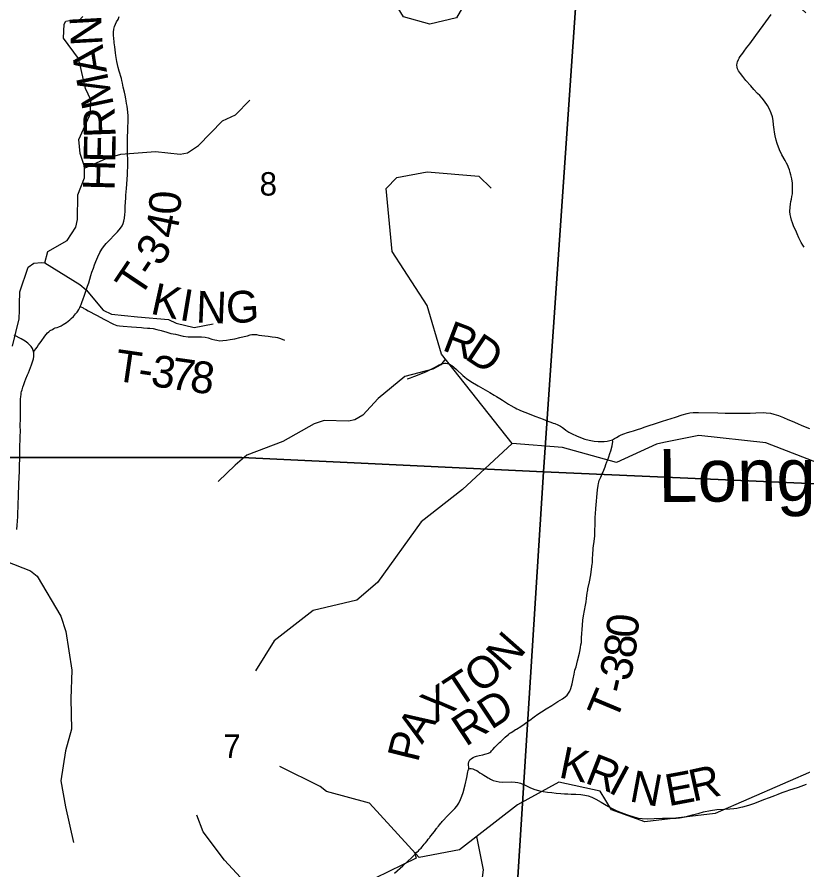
# Model space of a CAD drawing. Extents: x 0 to 34, y 0 to 22.
# Drawn here: x 25.483 to 26.889, y 16.271 to 17.797 of the extents above; entities that cross this region are included whole.
import ezdxf

# ---------------------------------------------------------------- set-up
doc = ezdxf.new("R2010")
doc.units = 0
for name, color, linetype in [('GM_X_County_Road', 7, 'Continuous'), ('GM_X_County_Road_Text', 7, 'Continuous'), ('GM_X_Minor_River', 7, 'Continuous'), ('GM_X_Minor_River_Text', 7, 'Continuous'), ('GM_X_Section', 7, 'Continuous'), ('GM_X_Section_Text', 7, 'Continuous'), ('GM_X_Township_Road', 7, 'Continuous'), ('GM_X_Township_Road_Text', 7, 'Continuous')]:
    doc.layers.add(name, color=color, linetype=linetype)

msp = doc.modelspace()

# ---------------------------------------------------------------- linework, layer by layer
at = {"layer": 'GM_X_County_Road'}
for points in [[(26.8908, 17.3848), (26.8887, 17.3883), (26.8856, 17.3932), (26.8818, 17.4015), (26.8787, 17.4086), (26.876, 17.4149), (26.8728, 17.4215), (26.87, 17.4287), (26.8685, 17.4334), (26.8671, 17.4387), (26.8659, 17.4435), (26.8654, 17.4488), (26.8658, 17.4566), (26.8667, 17.4622), (26.8675, 17.4669), (26.8683, 17.4711), (26.8692, 17.4757), (26.87, 17.4806), (26.8705, 17.4864), (26.8705, 17.4942), (26.8701, 17.4997), (26.8691, 17.5073), (26.8672, 17.5143), (26.866, 17.5186), (26.8646, 17.5234), (26.8632, 17.5273), (26.8616, 17.5314), (26.8596, 17.5354), (26.8573, 17.5398), (26.8514, 17.5502), (26.8472, 17.5593), (26.8427, 17.5702), (26.8409, 17.5763), (26.8392, 17.5844), (26.8382, 17.5908), (26.8375, 17.5957), (26.8365, 17.6037), (26.8356, 17.6115), (26.8343, 17.6179), (26.8322, 17.6246), (26.8291, 17.6317), (26.8253, 17.6386), (26.8202, 17.6463), (26.8158, 17.6516), (26.8116, 17.6562), (26.8077, 17.6602), (26.8013, 17.667), (26.7954, 17.6734), (26.787, 17.6833), (26.7811, 17.6905), (26.7769, 17.6959), (26.7737, 17.7006), (26.772, 17.7041), (26.7711, 17.7072), (26.7708, 17.7104), (26.771, 17.7143), (26.7716, 17.7168), (26.7733, 17.721), (26.7746, 17.7232), (26.7768, 17.7262), (26.7788, 17.7289), (26.7812, 17.7321), (26.7835, 17.7356), (26.7881, 17.7415), (26.7936, 17.7491), (26.8046, 17.7639), (26.8175, 17.7816), (26.8321, 17.8013)], [(25.4822, 16.88), (25.4829, 16.8874), (25.4835, 16.8948), (25.4839, 16.9029), (25.4842, 16.9128), (25.4843, 16.9171), (25.4845, 16.9252), (25.4849, 16.9395), (25.4858, 16.9618), (25.4867, 16.9842), (25.487, 16.9947), (25.4873, 17.0063), (25.4877, 17.0239), (25.4883, 17.0456), (25.4885, 17.0561), (25.4884, 17.0648), (25.4887, 17.0791), (25.4886, 17.1045), (25.4889, 17.1131), (25.4893, 17.118), (25.4897, 17.1211), (25.4901, 17.1241), (25.4908, 17.127), (25.4915, 17.13), (25.4929, 17.1347), (25.4946, 17.1393), (25.4965, 17.1445), (25.4984, 17.1491), (25.5013, 17.1564), (25.5031, 17.1604), (25.5048, 17.1646), (25.5068, 17.1698), (25.5086, 17.1744), (25.5104, 17.1797), (25.512, 17.1851), (25.5125, 17.1895), (25.5127, 17.192), (25.5125, 17.1958), (25.5121, 17.1978), (25.5116, 17.2001), (25.5103, 17.2036), (25.5079, 17.2074), (25.5063, 17.2093), (25.502, 17.2131), (25.497, 17.2168), (25.49, 17.2209), (25.4772, 17.2275)], [(26.291, 16.4508), (26.2917, 16.4514), (26.2932, 16.4519), (26.2951, 16.4522), (26.2983, 16.4516), (26.302, 16.45), (26.3051, 16.4483), (26.3078, 16.4467), (26.3109, 16.4446), (26.3143, 16.4424), (26.3181, 16.44), (26.3209, 16.4383), (26.3256, 16.4353), (26.3278, 16.434), (26.33, 16.4328), (26.3345, 16.4309), (26.3399, 16.4292), (26.3453, 16.4282), (26.3519, 16.4278), (26.3674, 16.4282), (26.3739, 16.4279), (26.3785, 16.4272), (26.3835, 16.4257), (26.3918, 16.4222), (26.3968, 16.4198), (26.4015, 16.4178), (26.409, 16.4147), (26.4155, 16.4128), (26.4201, 16.4118), (26.4241, 16.411), (26.4317, 16.4098), (26.4393, 16.4089), (26.4473, 16.408), (26.4557, 16.4074), (26.4622, 16.4069), (26.4684, 16.4067), (26.4742, 16.4065), (26.4822, 16.4063), (26.4913, 16.4056), (26.4984, 16.4047), (26.5048, 16.403), (26.5112, 16.4006), (26.5184, 16.3972), (26.5281, 16.3917), (26.534, 16.3883), (26.541, 16.3842), (26.5475, 16.3806), (26.556, 16.3765), (26.5635, 16.3733), (26.5732, 16.3696), (26.5784, 16.368), (26.5847, 16.3661), (26.5943, 16.3634), (26.6012, 16.3625), (26.6111, 16.3622), (26.6229, 16.3626), (26.6378, 16.3632), (26.6434, 16.3634), (26.6546, 16.3631), (26.662, 16.3633), (26.6682, 16.3639), (26.6781, 16.3657), (26.6914, 16.369), (26.6962, 16.3703), (26.703, 16.3721), (26.7111, 16.3743), (26.7232, 16.3768), (26.7351, 16.3785), (26.7475, 16.3794), (26.7582, 16.3802), (26.7651, 16.3808), (26.7704, 16.3813), (26.778, 16.383), (26.7814, 16.3837), (26.7918, 16.3867), (26.8027, 16.3903), (26.8191, 16.3964), (26.8288, 16.4001), (26.8389, 16.404), (26.8448, 16.4062), (26.8518, 16.4089), (26.8587, 16.4115), (26.8655, 16.4138), (26.8714, 16.4158), (26.8811, 16.419), (26.8954, 16.4243)], [(26.158, 16.2647), (26.1727, 16.2779), (26.1814, 16.2859), (26.1889, 16.293), (26.1947, 16.2986), (26.1982, 16.3023), (26.2009, 16.3048), (26.2024, 16.3065), (26.2041, 16.3082), (26.2057, 16.3098), (26.2068, 16.3111), (26.2075, 16.312), (26.2095, 16.3142), (26.2113, 16.3166), (26.2133, 16.3189), (26.2163, 16.3227), (26.2185, 16.3256), (26.2196, 16.3271), (26.2204, 16.328), (26.2215, 16.3294), (26.226, 16.3351), (26.2293, 16.3395), (26.2322, 16.3432), (26.2333, 16.3446), (26.2344, 16.346), (26.2351, 16.3469), (26.2365, 16.3488), (26.2386, 16.3514), (26.2408, 16.3542), (26.242, 16.3556), (26.2432, 16.357), (26.2445, 16.3583), (26.2456, 16.3597), (26.2469, 16.361), (26.2486, 16.3629), (26.2494, 16.3637), (26.2511, 16.3655), (26.2529, 16.3672), (26.2567, 16.3712), (26.2612, 16.3757), (26.2659, 16.3807), (26.2695, 16.385), (26.2729, 16.3902), (26.2762, 16.3967), (26.2787, 16.4028), (26.2807, 16.4092), (26.2843, 16.423), (26.2874, 16.436), (26.2892, 16.4463), (26.2897, 16.4488), (26.2904, 16.4503), (26.291, 16.4508)]]:
    msp.add_lwpolyline(points, dxfattribs=at)
at = {"layer": 'GM_X_Minor_River'}
for points in [[(26.8939, 17.8041), (26.8093, 17.8831), (26.7577, 17.9938), (26.6748, 18.0364), (26.663, 18.0393), (26.4885, 17.9971), (26.3926, 17.9568), (26.3196, 17.8836), (26.2691, 17.7955), (26.221, 17.7841), (26.1738, 17.7969), (26.1172, 17.8898)], [(25.4745, 17.2077), (25.4863, 17.2567), (25.487, 17.272), (25.487, 17.283), (25.4878, 17.305), (25.5022, 17.3492), (25.5128, 17.3564), (25.5261, 17.3576), (25.5325, 17.3572), (25.5375, 17.377), (25.572, 17.3971), (25.5875, 17.4207), (25.591, 17.4344), (25.5913, 17.4785), (25.6035, 17.509), (25.6035, 17.5291), (25.5952, 17.5523), (25.5933, 17.5778), (25.6122, 17.62), (25.6141, 17.6265), (25.6145, 17.6485), (25.6051, 17.669), (25.5956, 17.7108), (25.5926, 17.7226), (25.5657, 17.7591), (25.5668, 17.7842), (25.5699, 17.7895), (25.5763, 17.7907), (25.5934, 17.7899), (25.6002, 17.7975)], [(25.6035, 17.5265), (25.6419, 17.5439), (25.6682, 17.5511), (25.7302, 17.5563), (25.7746, 17.5516), (25.7876, 17.554), (25.8075, 17.5667), (25.8499, 17.6109), (25.8732, 17.622), (25.8991, 17.6483)], [(26.3684, 17.0338), (26.2421, 17.1937), (26.2163, 17.2807), (26.1539, 17.377), (26.1433, 17.49), (26.162, 17.5099), (26.2162, 17.5195), (26.3089, 17.512), (26.3308, 17.4905)], [(25.5325, 17.3572), (25.5947, 17.318), (25.6063, 17.3084), (25.6369, 17.2722), (25.6513, 17.2648), (25.6983, 17.2604), (25.7537, 17.2558), (25.7673, 17.2492), (25.7995, 17.2411), (25.8337, 17.2479)], [(26.249, 17.1849), (26.2407, 17.1743), (26.2265, 17.1665), (26.1762, 17.1535), (26.1285, 17.1139), (26.1015, 17.0846), (26.0873, 17.076), (26.0759, 17.0735), (26.0322, 17.0749), (26.0143, 17.0687), (25.958, 17.0372), (25.8935, 17.0126), (25.8727, 16.995), (25.8423, 16.9654)], [(26.9441, 16.9877), (26.8224, 17.0349), (26.7026, 17.0482), (26.6397, 17.0355), (26.6269, 17.0327), (26.5552, 16.9998), (26.4584, 17.0267), (26.3683, 17.0338), (26.2798, 16.9514), (26.2058, 16.8935), (26.1275, 16.785), (26.0907, 16.7535), (26.0124, 16.7346), (25.9425, 16.6805), (25.9094, 16.6266)], [(25.421, 16.8113), (25.4622, 16.8229), (25.5066, 16.8058), (25.5187, 16.796), (25.5607, 16.7249), (25.5698, 16.6975), (25.5804, 16.628), (25.5785, 16.5766), (25.58, 16.5226), (25.5694, 16.4835), (25.5606, 16.4302), (25.569, 16.3835), (25.5837, 16.32)], [(27.2498, 16.6488), (27.1456, 16.6153), (27.0809, 16.5676), (26.9976, 16.5244), (26.9124, 16.4504), (26.732, 16.3717), (26.6058, 16.3569), (26.5466, 16.378), (26.5261, 16.4116), (26.4522, 16.4277), (26.378, 16.3871), (26.2742, 16.3065), (26.2023, 16.293), (26.1133, 16.3901), (26.0364, 16.4107), (26.0249, 16.42), (25.953, 16.4558)], [(26.1935, 16.3026), (26.1966, 16.2917), (26.1235, 16.2558), (26.036, 16.2415), (26.0085, 16.2365), (25.9717, 16.2351), (25.9486, 16.2438), (25.8827, 16.2572), (25.8535, 16.288), (25.8155, 16.3387), (25.8045, 16.3689)], [(26.3049, 16.3303), (26.3169, 16.2708), (26.3031, 16.164), (26.2206, 15.9716), (26.2072, 15.921)]]:
    msp.add_lwpolyline(points, dxfattribs=at)
at = {"layer": 'GM_X_Section'}
for points in [[(25.4369, 18.0387), (25.9143, 18.0162), (26.4949, 18.0036), (26.4248, 16.9831), (25.8848, 17.0085), (25.3722, 17.0086), (25.3999, 17.4262), (25.4267, 17.8394)], [(26.4949, 18.0036), (27.546, 17.9583), (27.5355, 17.7931), (27.4974, 17.1618), (27.484, 16.9363), (26.4248, 16.9831)], [(26.4248, 16.9831), (26.3613, 15.9846), (25.3091, 16.0203), (25.3722, 17.0086), (25.8848, 17.0085)], [(27.484, 16.9363), (27.4673, 16.6748), (27.4216, 15.9328), (26.3734, 15.9843), (26.3613, 15.9846), (26.4248, 16.9831)]]:
    msp.add_lwpolyline(points, close=True, dxfattribs=at)
at = {"layer": 'GM_X_Township_Road'}
for points in [[(25.5121, 17.1978), (25.5183, 17.2062), (25.5212, 17.2102), (25.5257, 17.2161), (25.5324, 17.2258), (25.5369, 17.2315), (25.5392, 17.2336), (25.5419, 17.2357), (25.5457, 17.2379), (25.5484, 17.2392), (25.5509, 17.2404), (25.5541, 17.2415), (25.5572, 17.2424), (25.5615, 17.2444), (25.5652, 17.2464), (25.571, 17.25), (25.5742, 17.2526), (25.5768, 17.2551), (25.5796, 17.2575), (25.5834, 17.261), (25.5874, 17.2654), (25.5886, 17.267), (25.5903, 17.2689), (25.5914, 17.2706), (25.593, 17.2736), (25.5946, 17.2768), (25.5956, 17.2788), (25.5971, 17.2824), (25.5991, 17.2875), (25.6004, 17.291), (25.6033, 17.2991), (25.607, 17.3097), (25.6089, 17.3154), (25.6108, 17.3209), (25.6146, 17.334), (25.6166, 17.3401), (25.6191, 17.3475), (25.6214, 17.3535), (25.6235, 17.3591), (25.627, 17.3676), (25.6308, 17.3754), (25.6342, 17.3813), (25.637, 17.3853), (25.6422, 17.3915), (25.6489, 17.3988), (25.6559, 17.4058), (25.6623, 17.4125), (25.6674, 17.4187), (25.6705, 17.4234), (25.6725, 17.4273), (25.6739, 17.4315), (25.6749, 17.437), (25.6756, 17.4432), (25.6758, 17.4485), (25.676, 17.4538), (25.6763, 17.4594), (25.6765, 17.4637), (25.6767, 17.4661), (25.6771, 17.4725), (25.6775, 17.4779), (25.6784, 17.4899), (25.6801, 17.5143), (25.6806, 17.5345), (25.6806, 17.5412), (25.6803, 17.5517), (25.6802, 17.5554), (25.6801, 17.5659), (25.6803, 17.5833), (25.6805, 17.5919), (25.6808, 17.6011), (25.6813, 17.6078), (25.6816, 17.6134), (25.6814, 17.6198), (25.681, 17.6263), (25.6804, 17.6318), (25.6794, 17.6373), (25.6787, 17.6422), (25.6778, 17.647), (25.6771, 17.6507), (25.676, 17.6567), (25.6748, 17.6622), (25.6726, 17.6715), (25.671, 17.6786), (25.67, 17.6831), (25.6692, 17.6866), (25.6651, 17.7), (25.6635, 17.7066), (25.6622, 17.712), (25.6613, 17.7175), (25.6601, 17.7242), (25.6595, 17.7279), (25.659, 17.7328), (25.6575, 17.7437), (25.6565, 17.7506), (25.6563, 17.7536), (25.656, 17.7573), (25.6554, 17.7654), (25.6554, 17.7697), (25.6558, 17.7752), (25.657, 17.7799), (25.659, 17.7843), (25.6607, 17.7881), (25.6634, 17.7925), (25.6646, 17.7959), (25.6653, 17.7978)], [(25.5956, 17.2788), (25.6006, 17.2762), (25.6022, 17.2753), (25.6049, 17.2739), (25.6097, 17.2712), (25.6245, 17.2632), (25.6389, 17.2558), (25.6552, 17.2472), (25.661, 17.2449), (25.6656, 17.244), (25.6724, 17.2436), (25.6874, 17.2422), (25.7052, 17.241), (25.709, 17.2407), (25.7157, 17.2403), (25.7204, 17.2398), (25.726, 17.2392), (25.7326, 17.2379), (25.7404, 17.2357), (25.7505, 17.2326), (25.7575, 17.2305), (25.7658, 17.2291), (25.7799, 17.2259), (25.7888, 17.2246), (25.7967, 17.2244), (25.805, 17.2245), (25.8127, 17.2243), (25.819, 17.2237), (25.8248, 17.2227), (25.8314, 17.2206), (25.8362, 17.2193), (25.8403, 17.2184), (25.8455, 17.2175), (25.851, 17.2177), (25.8572, 17.2186), (25.8639, 17.2199), (25.872, 17.2212), (25.8815, 17.2232), (25.8891, 17.2249), (25.8949, 17.2266), (25.8997, 17.2279), (25.9029, 17.2285), (25.9064, 17.2287), (25.9108, 17.2285), (25.9153, 17.2278), (25.9207, 17.227), (25.9262, 17.2263), (25.9319, 17.2255), (25.9393, 17.2246), (25.9448, 17.2238), (25.9486, 17.2232), (25.9521, 17.2222), (25.9567, 17.2204), (25.9614, 17.2183)], [(26.1805, 17.1495), (26.1833, 17.1502), (26.1864, 17.1511), (26.1927, 17.1535), (26.196, 17.1549), (26.2151, 17.1625), (26.2295, 17.1698), (26.2382, 17.1745), (26.2428, 17.1764), (26.2477, 17.1776), (26.2501, 17.1777), (26.2531, 17.1771), (26.2565, 17.1756), (26.2603, 17.1733), (26.2643, 17.1701), (26.2688, 17.1659), (26.2803, 17.1555), (26.2841, 17.1523), (26.287, 17.15), (26.2947, 17.1447), (26.3075, 17.1371), (26.3283, 17.1247), (26.3363, 17.12), (26.3406, 17.1175), (26.3463, 17.114), (26.3512, 17.1111), (26.3568, 17.1076), (26.362, 17.1043), (26.3664, 17.1015), (26.3718, 17.0984), (26.374, 17.0973), (26.3767, 17.0959), (26.3801, 17.0944), (26.3835, 17.093), (26.3915, 17.0897), (26.4111, 17.0818), (26.4238, 17.077), (26.4326, 17.0738), (26.4378, 17.0719), (26.4419, 17.0703), (26.4448, 17.0693), (26.4505, 17.0669), (26.4548, 17.0645), (26.4584, 17.0622), (26.4609, 17.0604), (26.4646, 17.0578), (26.4702, 17.0541), (26.4762, 17.0509), (26.4837, 17.0475), (26.4908, 17.0443), (26.4988, 17.0414), (26.5066, 17.0395), (26.5153, 17.038), (26.5224, 17.0374), (26.5278, 17.0371), (26.533, 17.0371), (26.5388, 17.0379), (26.5436, 17.0391), (26.5482, 17.0405)], [(26.5482, 17.0405), (26.5519, 17.0424), (26.5554, 17.0445), (26.5603, 17.0476), (26.5635, 17.0494), (26.5681, 17.0511), (26.5751, 17.0534), (26.5817, 17.0553), (26.5858, 17.0566), (26.5929, 17.0588), (26.5988, 17.0608), (26.6065, 17.0633), (26.6306, 17.0713), (26.6377, 17.0736), (26.6608, 17.081), (26.6726, 17.0848), (26.6815, 17.0875), (26.6862, 17.0885), (26.6924, 17.0889), (26.7023, 17.089), (26.7364, 17.0885), (26.7495, 17.0882), (26.7638, 17.088), (26.7787, 17.0879), (26.7942, 17.0881), (26.8046, 17.0885), (26.8178, 17.0889), (26.8233, 17.0887), (26.8307, 17.0877), (26.8367, 17.0864), (26.8449, 17.0838), (26.8542, 17.0802), (26.8621, 17.0767), (26.8695, 17.0734), (26.8789, 17.0693), (26.8872, 17.0657), (26.9005, 17.0605)], [(26.291, 16.4508), (26.2908, 16.4535), (26.2903, 16.4591), (26.2903, 16.4609), (26.2904, 16.462), (26.2908, 16.4632), (26.2911, 16.4642), (26.2915, 16.465), (26.293, 16.4677), (26.2955, 16.4701), (26.2985, 16.472), (26.3013, 16.4732), (26.3048, 16.4744), (26.3094, 16.4755), (26.316, 16.4767), (26.3194, 16.4775), (26.322, 16.4781), (26.3262, 16.4796), (26.3284, 16.4807), (26.3304, 16.4822), (26.3315, 16.4835), (26.3324, 16.4843), (26.3339, 16.4861), (26.3376, 16.4902), (26.3407, 16.4932), (26.3424, 16.495), (26.346, 16.4984), (26.3482, 16.5006), (26.3563, 16.5083), (26.3595, 16.5112), (26.3617, 16.5132), (26.3626, 16.5139), (26.3646, 16.5152), (26.3667, 16.5164), (26.3696, 16.5185), (26.3748, 16.5217), (26.3764, 16.5226), (26.3842, 16.5275), (26.3898, 16.5314), (26.3949, 16.535), (26.3968, 16.5364), (26.4024, 16.5403), (26.4056, 16.5428), (26.408, 16.5447), (26.4145, 16.5491), (26.4212, 16.5534), (26.4295, 16.5586), (26.4397, 16.5649), (26.4505, 16.5719), (26.4584, 16.5769), (26.4636, 16.5804), (26.4669, 16.5834), (26.4696, 16.5869), (26.4718, 16.5908), (26.4736, 16.5954), (26.4747, 16.5996), (26.4759, 16.6039), (26.4778, 16.6126), (26.4795, 16.6209), (26.4809, 16.6283), (26.4828, 16.6341), (26.4855, 16.6449), (26.4891, 16.6588), (26.4902, 16.6646), (26.491, 16.6685), (26.4917, 16.6734), (26.4924, 16.6777), (26.4929, 16.6858), (26.4944, 16.7086), (26.4953, 16.7178), (26.4962, 16.7252), (26.4997, 16.7446), (26.5007, 16.7504), (26.5016, 16.7562), (26.503, 16.7662), (26.5034, 16.7688), (26.5038, 16.7716), (26.5042, 16.7736), (26.507, 16.7861), (26.5095, 16.7989), (26.5101, 16.8041), (26.5118, 16.8175), (26.5122, 16.8201), (26.5123, 16.823), (26.5124, 16.826), (26.5125, 16.8295), (26.5127, 16.8332), (26.5129, 16.8382), (26.5134, 16.8425), (26.5138, 16.8465), (26.5141, 16.8505), (26.5147, 16.8546), (26.5153, 16.8577), (26.5159, 16.8641), (26.5162, 16.867), (26.5164, 16.8728), (26.517, 16.8942), (26.5172, 16.902), (26.5174, 16.9079), (26.5181, 16.9175), (26.5213, 16.9508), (26.5222, 16.9585), (26.5228, 16.9621), (26.5234, 16.9646), (26.5243, 16.9674), (26.5271, 16.9736), (26.5298, 16.9792), (26.5326, 16.9861), (26.5348, 16.9919), (26.5363, 16.996), (26.5382, 17.0011), (26.5391, 17.0034), (26.5414, 17.0098), (26.5434, 17.0157), (26.545, 17.0204), (26.5475, 17.0294), (26.5483, 17.0334), (26.5485, 17.0369), (26.5482, 17.0405)]]:
    msp.add_lwpolyline(points, dxfattribs=at)

# ---------------------------------------------------------------- texts
at = {"layer": 'GM_X_County_Road_Text'}
for s, rotation, p in [('K', 348.4693, (26.4501, 16.4365)), ('R', 338.6244, (26.4966, 16.4272)), ('I', 331.7904, (26.5384, 16.4109)), ('R', 12.5034, (26.692, 16.3927)), ('N', 349.4188, (26.5766, 16.3937)), ('E', 10.5457, (26.6482, 16.3845))]:
    msp.add_text(s, height=0.0568, rotation=rotation, dxfattribs=at).set_placement(p)
at = {"layer": 'GM_X_Minor_River_Text'}
msp.add_text('Long', height=0.0947, rotation=0.5112, dxfattribs=at).set_placement((26.6304, 16.9288))
at = {"layer": 'GM_X_Section_Text'}
for s, p in [('8', (25.9166, 17.4773)), ('7', (25.8516, 16.4712))]:
    msp.add_text(s, height=0.0419, rotation=0, dxfattribs=at).set_placement(p)
at = {"layer": 'GM_X_Township_Road_Text'}
for s, height, rotation, p in [('N', 0.0568, 93.1707, (25.6358, 17.7466)), ('A', 0.0568, 98.976, (25.6435, 17.6987)), ('M', 0.0568, 101.9764, (25.6561, 17.6391)), ('R', 0.0568, 92.1144, (25.6591, 17.5819)), ('E', 0.0568, 88.7221, (25.6582, 17.5358)), ('H', 0.0568, 88.6192, (25.657, 17.4857)), ('0', 0.0568, 86.9958, (25.7747, 17.4422)), ('4', 0.0568, 78.2462, (25.7663, 17.3985)), ('3', 0.0568, 57.8282, (25.7395, 17.3485)), ('T', 0.0568, 56.159, (25.7019, 17.2923)), ('-', 0.0568, 56.2662, (25.7256, 17.3277)), ('K', 0.0568, 347.5755, (25.7194, 17.2664)), ('I', 0.0568, 350.5159, (25.7714, 17.255)), ('N', 0.0568, 357.5849, (25.802, 17.2504)), ('G', 0.0568, 3.4121, (25.8582, 17.2483)), ('R', 0.0568, 339.131, (26.2413, 17.2014)), ('D', 0.0568, 326.4024, (26.2819, 17.1863)), ('T', 0.0568, 351.6566, (25.6549, 17.1465)), ('3', 0.0568, 351.7154, (25.7201, 17.1369)), ('7', 0.0568, 351.8574, (25.7549, 17.1318)), ('8', 0.0568, 352.3329, (25.79, 17.1268)), ('-', 0.0568, 351.663, (25.6969, 17.1403)), ('0', 0.0568, 85.0182, (26.5928, 16.6844)), ('N', 0.0568, 48.6455, (26.3599, 16.6233)), ('8', 0.0568, 83.1109, (26.5883, 16.6476)), ('O', 0.0568, 36.3398, (26.3098, 16.5847)), ('3', 0.0568, 76.2446, (26.5787, 16.6063)), ('T', 0.0568, 33.3311, (26.2716, 16.5595)), ('X', 0.0568, 33.7896, (26.2302, 16.5318)), ('-', 0.0568, 76.9909, (26.5735, 16.5838)), ('T', 0.0568, 67.3056, (26.5539, 16.5346)), ('RD', 0.05682, 33.4162, (26.2853, 16.4903)), ('A', 0.0568, 56.9707, (26.2072, 16.4942)), ('P', 0.0568, 76.0358, (26.1999, 16.4615))]:
    msp.add_text(s, height=height, rotation=rotation, dxfattribs=at).set_placement(p)

doc.saveas('drawing.dxf')
